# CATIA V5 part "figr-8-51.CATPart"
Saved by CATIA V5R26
Part number: Part1
Bounding box of the stored display mesh (mm): x -75 to 75, y -75 to 75, z 0 to 10
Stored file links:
  D:\_Deepak\CATIA\CATIA V5-6R2016_Deepak\Resources\Part files\Partfiles\c08_catia_v5_6r2016_prt\figr-8-51.CATPart
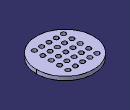
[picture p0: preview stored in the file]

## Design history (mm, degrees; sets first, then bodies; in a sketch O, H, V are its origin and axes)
Body1 (main body)
  Sketch1 on xy-plane, origin (0, 0, 0), H (1, 0, 0), V (0, 1, 0)
    circle A1 centre (0, 0) radius 75
    point P1 (0, 75)
    radius A1 = 75
    coincidence: A1 P1, P1 V
  Pad1: profile Sketch1, direction (0, 0, 1), length 10
  Sketch2 on face of Pad1, origin (0, 0, 10), H (1, 0, 0), V (0, 1, 0)
    circle A1 centre (35, -45) radius 6
    point P1 (35, -45)
    distance P1 H = 45
    distance V P1 = 35
    radius A1 = 6
  Pocket1: profile Sketch2, direction (0, 0, -1), through (limit type 3)
  RectPattern1: of Pocket1, direction 1 instances 5, spacing 19, along xy-plane reversed, direction 2 instances 5, spacing 22, along xy-plane
  Affinity1: ToTransfor RectPattern1, RatioX 1, RatioY 1, RatioZ 1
